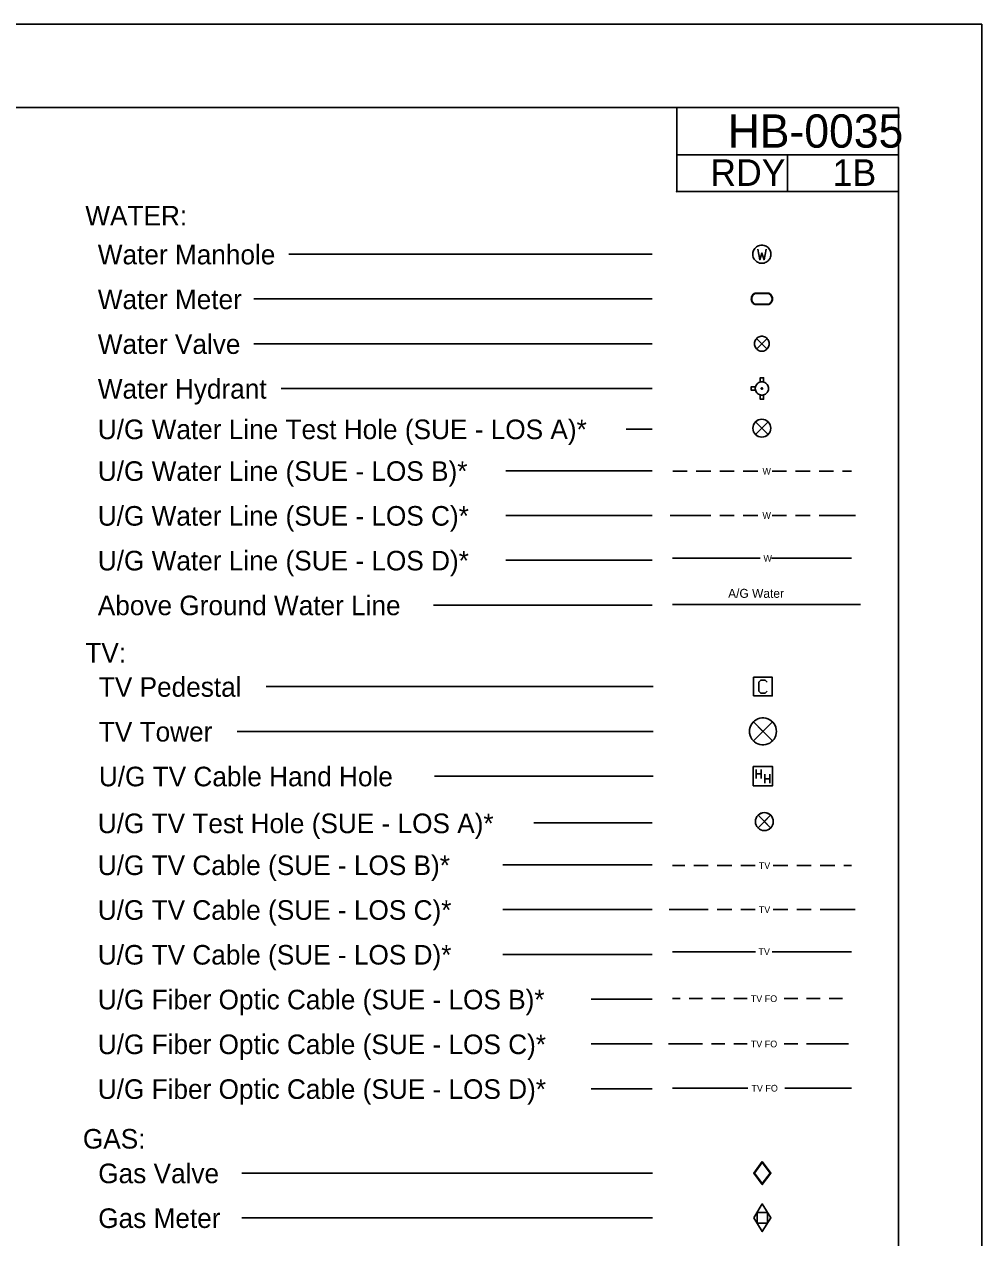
# Model space of a CAD drawing. Extents: x 754056.72 to 754059.56, y 596603.78 to 596605.61.
# Drawn here: x 754058.839 to 754059.558, y 596604.7 to 596605.612 of the extents above; entities that cross this region are included whole.
import ezdxf

# ---------------------------------------------------------------- set-up
doc = ezdxf.new("R2010")
doc.units = 0
for name, color, linetype in [('Exist Utilities TV Test Hole SUE LOS A CELL', 7, 'Continuous'), ('Exist Utilities Water Test Hole SUE LOS A CELL', 7, 'Continuous'), ('Sheet_Plan', 7, 'Continuous'), ('Sheet_Plot_Border_Outside_CELL', 7, 'Continuous'), ('Sheet_Symbology', 7, 'Continuous'), ('Sheet_Title_Block_Text', 7, 'Continuous'), ('z - Construction', 7, 'Continuous')]:
    doc.layers.add(name, color=color, linetype=linetype)

msp = doc.modelspace()

# ---------------------------------------------------------------- linework, layer by layer
at = {"layer": 'Exist Utilities TV Test Hole SUE LOS A CELL'}
for points in [[(754059.39958, 596605.01736), (754059.39008, 596605.00786), (754059.39483, 596605.01261), (754059.39008, 596605.01736), (754059.39958, 596605.00786)], [(754059.39008, 596605.01736), (754059.39483, 596605.01261), (754059.39958, 596605.01736)], [(754059.39958, 596605.00786), (754059.39483, 596605.01261), (754059.39008, 596605.00786)]]:
    msp.add_lwpolyline(points, dxfattribs=at)
msp.add_circle((754059.39483, 596605.01261), 0.00672, dxfattribs=at)
for start, end in [(45, 135), (225, 315)]:
    msp.add_arc((754059.39483, 596605.01261), 0.00672, start, end, dxfattribs=at)
at = {"layer": 'Exist Utilities Water Test Hole SUE LOS A CELL'}
for points in [[(754059.39766, 596605.31289), (754059.38815, 596605.30339), (754059.39291, 596605.30814), (754059.38815, 596605.31289), (754059.39766, 596605.30339)], [(754059.38815, 596605.31289), (754059.39291, 596605.30814), (754059.39766, 596605.31289)], [(754059.39766, 596605.30339), (754059.39291, 596605.30814), (754059.38815, 596605.30339)]]:
    msp.add_lwpolyline(points, dxfattribs=at)
msp.add_circle((754059.39291, 596605.30814), 0.00672, dxfattribs=at)
for start, end in [(45, 135), (225, 315)]:
    msp.add_arc((754059.39291, 596605.30814), 0.00672, start, end, dxfattribs=at)
at = {"layer": 'Sheet_Plan'}
for p, q in [((754059.49567, 596605.54909), (754056.78733, 596605.54909)), ((754059.329, 596605.48589), (754059.329, 596605.54909)), ((754059.49562, 596603.84076), (754059.49567, 596605.54909)), ((754059.49567, 596605.51339), (754059.329, 596605.51339)), ((754059.41233, 596605.48589), (754059.41233, 596605.51339)), ((754059.49567, 596605.48589), (754059.329, 596605.48589))]:
    msp.add_line(p, q, dxfattribs=at)
msp.add_circle((754059.329, 596605.48589), 0.0001, dxfattribs=at)
at = {"layer": 'Sheet_Plot_Border_Outside_CELL'}
msp.add_line((754059.55817, 596603.77826), (754059.55817, 596605.61159), dxfattribs=at)
msp.add_lwpolyline([(754056.72484, 596605.61159), (754059.55817, 596605.61159), (754059.55817, 596603.77826), (754056.72484, 596603.77826)], close=True, dxfattribs=at)
at = {"layer": 'Sheet_Symbology'}
for p, q in [((754059.31055, 596605.43885), (754059.03748, 596605.43885)), ((754059.31055, 596605.40522), (754059.01117, 596605.40522)), ((754059.38783, 596605.40954), (754059.39817, 596605.40954)), ((754059.38783, 596605.40921), (754059.39817, 596605.40921)), ((754059.3981, 596605.40131), (754059.38783, 596605.40131)), ((754059.3981, 596605.40097), (754059.38783, 596605.40097)), ((754059.31055, 596605.37159), (754059.01117, 596605.37159)), ((754059.31055, 596605.33796), (754059.03177, 596605.33796)), ((754059.31055, 596605.30754), (754059.29113, 596605.30754)), ((754059.31055, 596605.27619), (754059.20061, 596605.27619)), ((754059.32598, 596605.27583), (754059.33691, 596605.27583)), ((754059.34363, 596605.27583), (754059.35456, 596605.27583)), ((754059.36129, 596605.27583), (754059.37222, 596605.27583)), ((754059.37895, 596605.27583), (754059.38988, 596605.27583)), ((754059.40064, 596605.27583), (754059.41157, 596605.27583)), ((754059.41829, 596605.27583), (754059.42922, 596605.27583)), ((754059.43595, 596605.27583), (754059.44688, 596605.27583)), ((754059.45361, 596605.27583), (754059.46023, 596605.27583)), ((754059.31055, 596605.24256), (754059.20061, 596605.24256)), ((754059.32407, 596605.24256), (754059.35456, 596605.24256)), ((754059.36129, 596605.24256), (754059.37222, 596605.24256)), ((754059.37895, 596605.24256), (754059.38988, 596605.24256)), ((754059.40064, 596605.24256), (754059.41157, 596605.24256)), ((754059.41829, 596605.24256), (754059.42922, 596605.24256)), ((754059.43595, 596605.24256), (754059.46338, 596605.24256)), ((754059.31055, 596605.20893), (754059.20061, 596605.20893)), ((754059.3257, 596605.21041), (754059.39179, 596605.21041)), ((754059.4002, 596605.21041), (754059.46023, 596605.21041)), ((754059.31055, 596605.1753), (754059.14624, 596605.1753)), ((754059.3257, 596605.17566), (754059.46698, 596605.17566)), ((754059.31135, 596605.11402), (754059.02059, 596605.11402)), ((754059.39271, 596605.10907), (754059.39488, 596605.10907)), ((754059.31135, 596605.08039), (754058.99885, 596605.08039)), ((754059.31135, 596605.04675), (754059.14704, 596605.04675)), ((754059.38862, 596605.05184), (754059.38862, 596605.04507)), ((754059.38862, 596605.04839), (754059.39249, 596605.04839)), ((754059.39249, 596605.05184), (754059.39249, 596605.04507)), ((754059.39508, 596605.04815), (754059.39508, 596605.04137)), ((754059.39896, 596605.04815), (754059.39896, 596605.04137)), ((754059.39508, 596605.0447), (754059.39896, 596605.0447)), ((754059.31055, 596605.01155), (754059.22166, 596605.01155)), ((754059.31055, 596604.98008), (754059.19841, 596604.98008)), ((754059.3257, 596604.97954), (754059.33508, 596604.97954)), ((754059.3418, 596604.97954), (754059.35273, 596604.97954)), ((754059.35946, 596604.97954), (754059.37039, 596604.97954)), ((754059.37712, 596604.97954), (754059.38805, 596604.97954)), ((754059.4015, 596604.97954), (754059.41243, 596604.97954)), ((754059.41916, 596604.97954), (754059.43009, 596604.97954)), ((754059.43681, 596604.97954), (754059.44774, 596604.97954)), ((754059.45447, 596604.97954), (754059.46023, 596604.97954)), ((754059.31055, 596604.94645), (754059.19841, 596604.94645)), ((754059.32338, 596604.94645), (754059.35273, 596604.94645)), ((754059.35946, 596604.94645), (754059.37039, 596604.94645)), ((754059.37712, 596604.94645), (754059.38805, 596604.94645)), ((754059.4015, 596604.94645), (754059.41243, 596604.94645)), ((754059.41916, 596604.94645), (754059.43009, 596604.94645)), ((754059.43681, 596604.94645), (754059.46306, 596604.94645)), ((754059.31055, 596604.91282), (754059.19841, 596604.91282)), ((754059.3257, 596604.91486), (754059.38822, 596604.91486)), ((754059.40083, 596604.91486), (754059.46023, 596604.91486)), ((754059.31055, 596604.87919), (754059.26475, 596604.87919)), ((754059.3257, 596604.87959), (754059.33159, 596604.87959)), ((754059.33832, 596604.87959), (754059.3484, 596604.87959)), ((754059.35513, 596604.87959), (754059.36522, 596604.87959)), ((754059.37195, 596604.87959), (754059.38204, 596604.87959)), ((754059.40978, 596604.87959), (754059.41987, 596604.87959)), ((754059.4266, 596604.87959), (754059.43669, 596604.87959)), ((754059.44341, 596604.87959), (754059.4535, 596604.87959)), ((754059.31055, 596604.84556), (754059.26475, 596604.84556)), ((754059.32294, 596604.84556), (754059.3484, 596604.84556)), ((754059.35513, 596604.84556), (754059.36522, 596604.84556)), ((754059.37195, 596604.84556), (754059.38204, 596604.84556)), ((754059.40978, 596604.84556), (754059.41987, 596604.84556)), ((754059.4266, 596604.84556), (754059.45809, 596604.84556)), ((754059.31055, 596604.81192), (754059.26475, 596604.81192)), ((754059.3257, 596604.81232), (754059.38252, 596604.81232)), ((754059.41027, 596604.81232), (754059.46023, 596604.81232)), ((754059.39331, 596604.75652), (754059.3874, 596604.74858)), ((754059.39922, 596604.74858), (754059.39331, 596604.75652)), ((754059.31089, 596604.74858), (754059.00235, 596604.74858)), ((754059.3874, 596604.74858), (754059.39331, 596604.74065)), ((754059.39331, 596604.74065), (754059.39922, 596604.74858)), ((754059.31089, 596604.71495), (754059.00235, 596604.71495))]:
    msp.add_line(p, q, dxfattribs=at)
for points in [[(754059.39297, 596605.44568), (754059.39209, 596605.44563), (754059.39127, 596605.44546), (754059.39045, 596605.44519), (754059.38969, 596605.44481), (754059.38898, 596605.44437), (754059.38832, 596605.44382), (754059.38772, 596605.44317), (754059.38723, 596605.44251), (754059.38679, 596605.44175), (754059.38652, 596605.44093), (754059.3863, 596605.44011), (754059.38619, 596605.43929), (754059.38619, 596605.43842), (754059.3863, 596605.4376), (754059.38652, 596605.43673), (754059.38679, 596605.43596), (754059.38723, 596605.43519), (754059.38772, 596605.43454), (754059.38832, 596605.43388), (754059.38898, 596605.43334), (754059.38969, 596605.4329), (754059.39045, 596605.43252), (754059.39127, 596605.43224), (754059.39215, 596605.43208), (754059.39297, 596605.43203), (754059.39384, 596605.43208), (754059.39466, 596605.43224), (754059.39548, 596605.43252), (754059.39624, 596605.4329), (754059.39695, 596605.43334), (754059.39761, 596605.43388), (754059.39821, 596605.43454), (754059.3987, 596605.43519), (754059.39914, 596605.43596), (754059.39941, 596605.43678), (754059.39963, 596605.4376), (754059.39974, 596605.43842), (754059.39974, 596605.43929), (754059.39963, 596605.44011), (754059.39941, 596605.44098), (754059.39914, 596605.44175), (754059.3987, 596605.44251), (754059.39821, 596605.44317), (754059.39761, 596605.44382), (754059.39695, 596605.44437), (754059.39624, 596605.44481), (754059.39548, 596605.44519), (754059.39466, 596605.44546), (754059.39379, 596605.44563), (754059.39297, 596605.44568)], [(754059.38991, 596605.44262), (754059.39133, 596605.43465), (754059.39297, 596605.43967), (754059.39466, 596605.43465), (754059.39608, 596605.44262)], [(754059.38783, 596605.40954), (754059.38716, 596605.40921), (754059.38655, 596605.40873), (754059.38601, 596605.40813), (754059.38561, 596605.40752), (754059.38527, 596605.40678), (754059.38507, 596605.40603), (754059.385, 596605.40529), (754059.38507, 596605.40448), (754059.38527, 596605.40374), (754059.38561, 596605.40306), (754059.38601, 596605.40239), (754059.38655, 596605.40185), (754059.38716, 596605.40137), (754059.38783, 596605.40097)], [(754059.38797, 596605.40927), (754059.38729, 596605.40887), (754059.38669, 596605.4084), (754059.38615, 596605.40779), (754059.38574, 596605.40718), (754059.38547, 596605.40644), (754059.38533, 596605.40563), (754059.38533, 596605.40489), (754059.38547, 596605.40414), (754059.38574, 596605.4034), (754059.38615, 596605.40272), (754059.38669, 596605.40212), (754059.38729, 596605.40164), (754059.38797, 596605.40131)], [(754059.39796, 596605.40927), (754059.39871, 596605.40894), (754059.39931, 596605.4084), (754059.39979, 596605.40785), (754059.40019, 596605.40718), (754059.40046, 596605.40644), (754059.4006, 596605.40563), (754059.4006, 596605.40489), (754059.40046, 596605.40408), (754059.40019, 596605.4034), (754059.39979, 596605.40272), (754059.39925, 596605.40212), (754059.39864, 596605.40164), (754059.39796, 596605.40124)], [(754059.3981, 596605.40954), (754059.39877, 596605.40921), (754059.39938, 596605.40873), (754059.39992, 596605.40813), (754059.40033, 596605.40752), (754059.40067, 596605.40678), (754059.40087, 596605.40603), (754059.40094, 596605.40529), (754059.40087, 596605.40448), (754059.40067, 596605.40374), (754059.40033, 596605.40306), (754059.39992, 596605.40239), (754059.39938, 596605.40185), (754059.39877, 596605.40137), (754059.3981, 596605.40097)], [(754059.39855, 596605.37159), (754059.39849, 596605.3724), (754059.3983, 596605.37327), (754059.39799, 596605.37401), (754059.39756, 596605.37476), (754059.39706, 596605.37538), (754059.39644, 596605.37594), (754059.39576, 596605.37643), (754059.39501, 596605.3768), (754059.39421, 596605.37706), (754059.3934, 596605.37718), (754059.39253, 596605.37718), (754059.39173, 596605.37706), (754059.39092, 596605.3768), (754059.39017, 596605.37643), (754059.38949, 596605.37594), (754059.38887, 596605.37538), (754059.38837, 596605.37476), (754059.38794, 596605.37401), (754059.38763, 596605.37327), (754059.38744, 596605.3724), (754059.38738, 596605.37159), (754059.38744, 596605.37079), (754059.38763, 596605.36992), (754059.38794, 596605.36917), (754059.38837, 596605.36843), (754059.38887, 596605.3678), (754059.38949, 596605.36725), (754059.39017, 596605.36675), (754059.39092, 596605.36638), (754059.39173, 596605.36613), (754059.39253, 596605.36601), (754059.3934, 596605.36601), (754059.39421, 596605.36613), (754059.39501, 596605.36638), (754059.39576, 596605.36675), (754059.39644, 596605.36725), (754059.39706, 596605.3678), (754059.39756, 596605.36843), (754059.39799, 596605.36917), (754059.3983, 596605.36992), (754059.39849, 596605.37079), (754059.39855, 596605.37159)], [(754059.39694, 596605.36762), (754059.38899, 596605.37556), (754059.39297, 596605.37159), (754059.38899, 596605.36762), (754059.39694, 596605.37556)], [(754059.38819, 596605.33925), (754059.38496, 596605.33925), (754059.38496, 596605.33667), (754059.38819, 596605.33667)], [(754059.3929, 596605.34293), (754059.39213, 596605.34287), (754059.39135, 596605.34267), (754059.39058, 596605.34235), (754059.38993, 596605.3419), (754059.38935, 596605.34138), (754059.38884, 596605.34074), (754059.38845, 596605.34003), (754059.38819, 596605.33925), (754059.388, 596605.33848), (754059.388, 596605.3377), (754059.38812, 596605.33693), (754059.38832, 596605.33615), (754059.38871, 596605.33544), (754059.38916, 596605.3348), (754059.38974, 596605.33422), (754059.39038, 596605.3337), (754059.39109, 596605.33338), (754059.39187, 596605.33312), (754059.39264, 596605.33299), (754059.39342, 596605.33299), (754059.39419, 596605.33312), (754059.39497, 596605.33344), (754059.39568, 596605.33377), (754059.39632, 596605.33428), (754059.39684, 596605.33486), (754059.39729, 596605.33551), (754059.39761, 596605.33628), (754059.39787, 596605.33706), (754059.39794, 596605.33783), (754059.39787, 596605.33861), (754059.39774, 596605.33938), (754059.39742, 596605.34016), (754059.39703, 596605.34087), (754059.39652, 596605.34145), (754059.39587, 596605.34196), (754059.39523, 596605.34242), (754059.39445, 596605.34267), (754059.39368, 596605.34287), (754059.3929, 596605.34293)], [(754059.39174, 596605.3428), (754059.39174, 596605.34603), (754059.39432, 596605.34603), (754059.39432, 596605.34274)], [(754059.39297, 596605.33854), (754059.39271, 596605.33848), (754059.39251, 596605.33828), (754059.39239, 596605.33802), (754059.39245, 596605.33777), (754059.39258, 596605.33751), (754059.39284, 596605.33738), (754059.3931, 596605.33738), (754059.39335, 596605.33751), (754059.39348, 596605.33777), (754059.39355, 596605.33802), (754059.39342, 596605.33828), (754059.39322, 596605.33848), (754059.39297, 596605.33854)], [(754059.39174, 596605.33312), (754059.39174, 596605.32989), (754059.39432, 596605.32989), (754059.39432, 596605.33319)], [(754059.38676, 596605.10701), (754059.40078, 596605.10701), (754059.40078, 596605.12102), (754059.38676, 596605.12102), (754059.38676, 596605.10701)], [(754059.39705, 596605.11062), (754059.39538, 596605.10907), (754059.39216, 596605.10907), (754059.3906, 596605.11062), (754059.3906, 596605.11741), (754059.39216, 596605.11896), (754059.39538, 596605.11896), (754059.39705, 596605.11741)], [(754059.4039, 596605.08039), (754059.40379, 596605.08185), (754059.40345, 596605.08342), (754059.40288, 596605.08477), (754059.4021, 596605.08613), (754059.4012, 596605.08725), (754059.40007, 596605.08826), (754059.39884, 596605.08916), (754059.39748, 596605.08984), (754059.39602, 596605.09029), (754059.39456, 596605.09051), (754059.39298, 596605.09051), (754059.39152, 596605.09029), (754059.39006, 596605.08984), (754059.3887, 596605.08916), (754059.38747, 596605.08826), (754059.38634, 596605.08725), (754059.38544, 596605.08613), (754059.38466, 596605.08477), (754059.38409, 596605.08342), (754059.38375, 596605.08185), (754059.38364, 596605.08039), (754059.38375, 596605.07892), (754059.38409, 596605.07735), (754059.38466, 596605.076), (754059.38544, 596605.07464), (754059.38634, 596605.07352), (754059.38747, 596605.07251), (754059.3887, 596605.07161), (754059.39006, 596605.07093), (754059.39152, 596605.07048), (754059.39298, 596605.07026), (754059.39456, 596605.07026), (754059.39602, 596605.07048), (754059.39748, 596605.07093), (754059.39884, 596605.07161), (754059.40007, 596605.07251), (754059.4012, 596605.07352), (754059.4021, 596605.07464), (754059.40288, 596605.076), (754059.40345, 596605.07735), (754059.40379, 596605.07892), (754059.4039, 596605.08039)], [(754059.40097, 596605.07318), (754059.38657, 596605.08759), (754059.39377, 596605.08039), (754059.38657, 596605.07318), (754059.40097, 596605.08759)], [(754059.38653, 596605.03952), (754059.40101, 596605.03952), (754059.40101, 596605.05399), (754059.38653, 596605.05399), (754059.38653, 596605.03952)], [(754059.39331, 596604.75719), (754059.3869, 596604.74858), (754059.39331, 596604.73997), (754059.39973, 596604.74858), (754059.39331, 596604.75719)], [(754059.3869, 596604.71495), (754059.39331, 596604.72533), (754059.39973, 596604.71495), (754059.39331, 596604.70457), (754059.3869, 596604.71495)], [(754059.38934, 596604.71884), (754059.39728, 596604.71884), (754059.39728, 596604.71098), (754059.38934, 596604.71098), (754059.38934, 596604.71884)]]:
    msp.add_lwpolyline(points, dxfattribs=at)
at = {"layer": 'z - Construction'}
msp.add_line((754059.55817, 596605.61159), (754056.72484, 596605.61159), dxfattribs=at)

# ---------------------------------------------------------------- texts
at = {"layer": 'Sheet_Symbology'}
for s, height, p in [('WATER:', 0.014714, (754058.88466, 596605.46044)), ('Water Manhole', 0.0147137, (754058.89403, 596605.43122)), ('Water Meter', 0.0147137, (754058.89403, 596605.39759)), ('Water Valve', 0.0147137, (754058.89403, 596605.36396)), ('Water Hydrant', 0.0147137, (754058.89403, 596605.33033)), ('U/G Water Line Test Hole (SUE - LOS A)*', 0.0147137, (754058.89403, 596605.29991)), ('U/G Water Line (SUE - LOS B)*', 0.0147137, (754058.89403, 596605.26856)), ('W', 0.00504, (754059.39341, 596605.27331)), ('U/G Water Line (SUE - LOS C)*', 0.0147137, (754058.89403, 596605.23493)), ('W', 0.00504, (754059.39341, 596605.24004)), ('U/G Water Line (SUE - LOS D)*', 0.0147137, (754058.89403, 596605.2013)), ('W', 0.00504, (754059.39414, 596605.20788)), ('A/G Water', 0.006726, (754059.36762, 596605.18071)), ('Above Ground Water Line', 0.0147137, (754058.89403, 596605.16767)), ('TV:', 0.014714, (754058.88466, 596605.13209)), ('TV Pedestal', 0.0147137, (754058.89483, 596605.10639)), ('TV Tower', 0.014714, (754058.89483, 596605.07275)), ('U/G TV Cable Hand Hole', 0.0147137, (754058.89483, 596605.03912)), ('U/G TV Test Hole (SUE - LOS A)*', 0.0147137, (754058.89403, 596605.00392)), ('U/G TV Cable (SUE - LOS B)*', 0.0147137, (754058.89403, 596604.97245)), ('TV', 0.005045, (754059.39065, 596604.97702)), ('U/G TV Cable (SUE - LOS C)*', 0.0147137, (754058.89403, 596604.93882)), ('TV', 0.005045, (754059.39065, 596604.94393)), ('U/G TV Cable (SUE - LOS D)*', 0.0147137, (754058.89403, 596604.90519)), ('TV', 0.005045, (754059.3904, 596604.91233)), ('U/G Fiber Optic Cable (SUE - LOS B)*', 0.0147137, (754058.89403, 596604.87156)), ('TV FO', 0.005045, (754059.38464, 596604.87707)), ('U/G Fiber Optic Cable (SUE - LOS C)*', 0.0147137, (754058.89403, 596604.83793)), ('TV FO', 0.005045, (754059.38464, 596604.84303)), ('U/G Fiber Optic Cable (SUE - LOS D)*', 0.0147137, (754058.89403, 596604.80429)), ('TV FO', 0.005045, (754059.38513, 596604.8098)), ('GAS:', 0.014714, (754058.88282, 596604.76696)), ('Gas Valve', 0.014714, (754058.89437, 596604.74095)), ('Gas Meter', 0.014714, (754058.89437, 596604.70732))]:
    msp.add_text(s, height=height, dxfattribs=at).set_placement(p)
at = {"layer": 'Sheet_Title_Block_Text'}
for s, height, p in [('HB-0035', 0.025, (754059.3673, 596605.51888)), ('RDY', 0.02, (754059.35424, 596605.49016)), ('1B', 0.02, (754059.44616, 596605.49016))]:
    msp.add_text(s, height=height, dxfattribs=at).set_placement(p)

doc.saveas('drawing.dxf')
